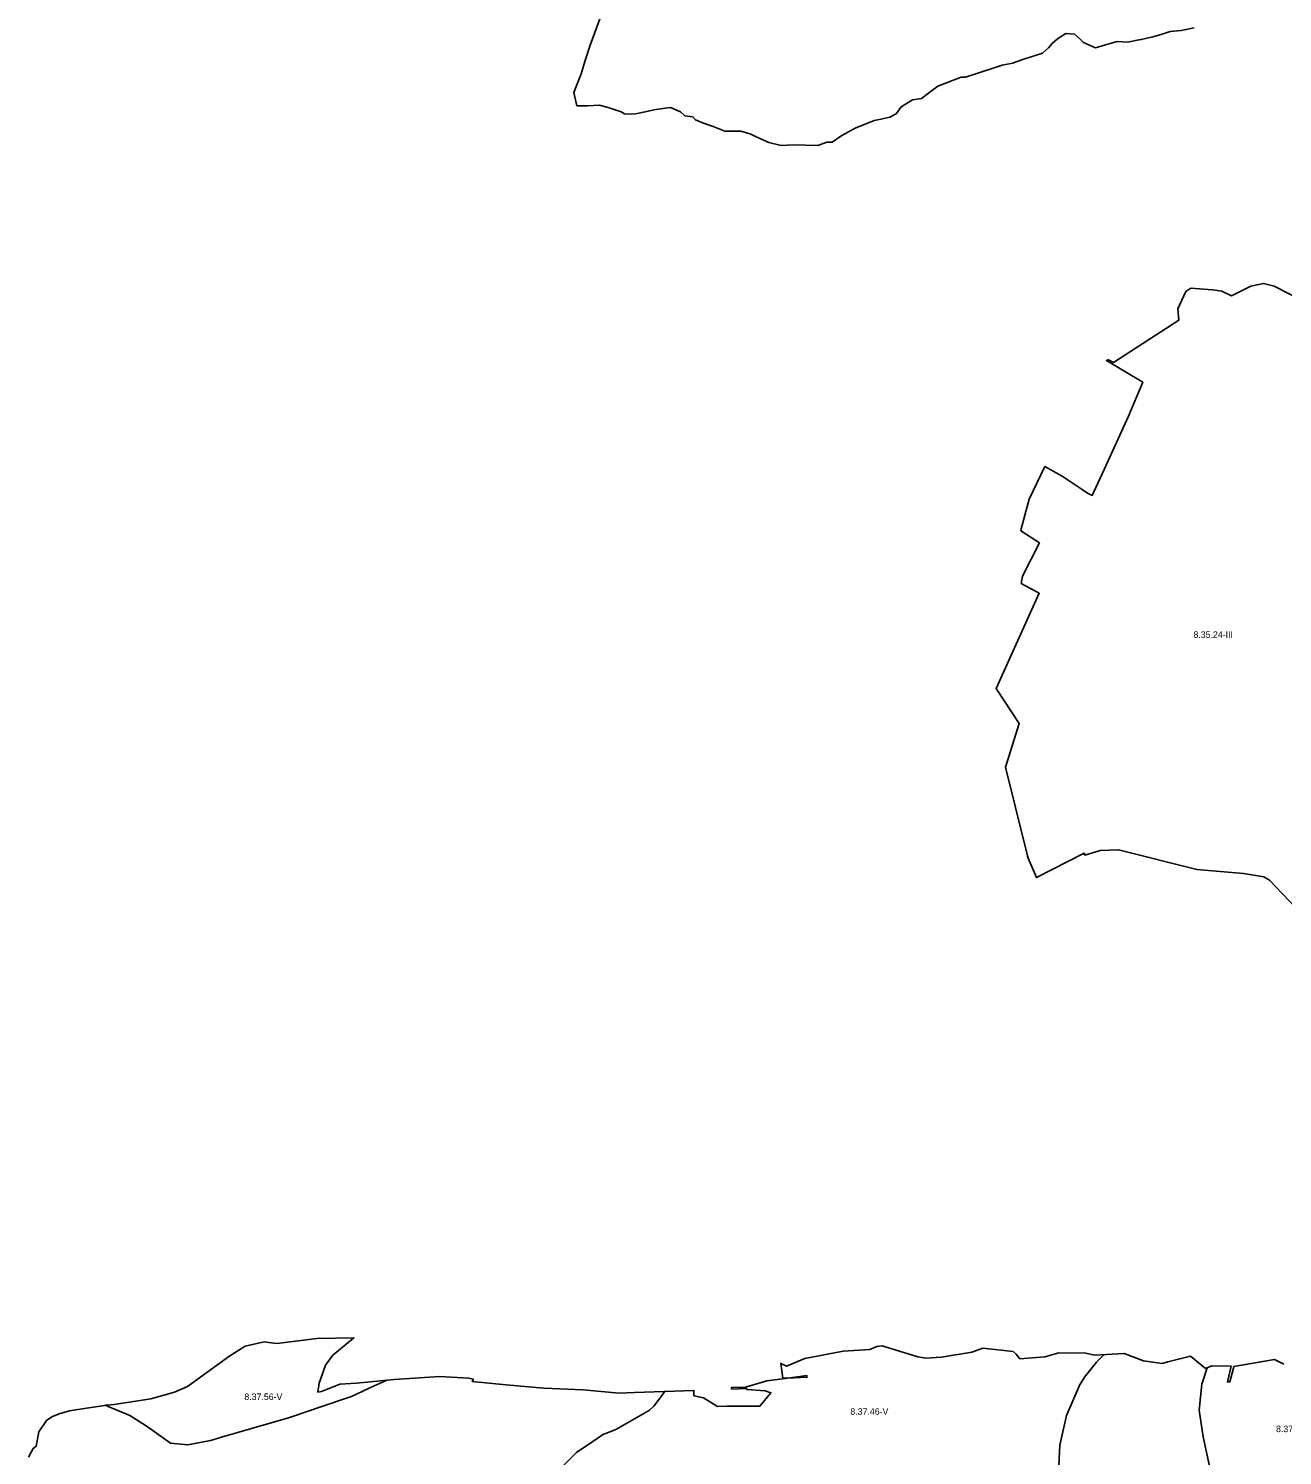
# Model space of a CAD drawing. Extents: x -547623 to -533936, y -1096714 to -1086523.
# Drawn here: x -544698 to -542784, y -1092367 to -1090189 of the extents above; entities that cross this region are included whole.
import ezdxf

# ---------------------------------------------------------------- set-up
doc = ezdxf.new("R2010")
doc.units = 0
doc.layers.add('Vrstva 27', color=7, linetype='Continuous')
doc.layers.add('Vrstva 28', color=7, linetype='Continuous')

msp = doc.modelspace()

# ---------------------------------------------------------------- linework, layer by layer
at = {"layer": 'Vrstva 28'}
for p, q in [((-543086, -1092247.5), (-543068, -1092224.5)), ((-543068, -1092224.5), (-543086, -1092247.5)), ((-543068, -1092224.5), (-543056.1, -1092213.1)), ((-543056.1, -1092213.1), (-543068, -1092224.5)), ((-542898.7, -1092233.1), (-542905.6, -1092253.4)), ((-542905.6, -1092253.4), (-542898.7, -1092233.1)), ((-544170.1, -1092260.9), (-544158.7, -1092255.7)), ((-544158.7, -1092255.7), (-544170.1, -1092260.9)), ((-544158.7, -1092255.7), (-544150.8, -1092252.1)), ((-544150.8, -1092252.1), (-544158.7, -1092255.7)), ((-543094.3, -1092260.6), (-543086, -1092247.5)), ((-543086, -1092247.5), (-543094.3, -1092260.6)), ((-542905.6, -1092253.4), (-542907, -1092257.5)), ((-542907, -1092257.5), (-542905.6, -1092253.4)), ((-544259.4, -1092295.4), (-544205, -1092277)), ((-544205, -1092277), (-544259.4, -1092295.4)), ((-544205, -1092277), (-544170.1, -1092260.9)), ((-544170.1, -1092260.9), (-544205, -1092277)), ((-543731.3, -1092275.6), (-543743, -1092291)), ((-543743, -1092291), (-543731.3, -1092275.6)), ((-543726.6, -1092269.4), (-543731.3, -1092275.6)), ((-543731.3, -1092275.6), (-543726.6, -1092269.4)), ((-543113.5, -1092306), (-543096, -1092264.6)), ((-543096, -1092264.6), (-543113.5, -1092306)), ((-543096, -1092264.6), (-543094.5, -1092261)), ((-543094.5, -1092261), (-543096, -1092264.6)), ((-543094.5, -1092261), (-543094.3, -1092260.6)), ((-543094.3, -1092260.6), (-543094.5, -1092261)), ((-542907, -1092258), (-542911, -1092298)), ((-542911, -1092298), (-542907, -1092258)), ((-542907, -1092257.5), (-542907, -1092258)), ((-542907, -1092258), (-542907, -1092257.5)), ((-544580.3, -1092290.3), (-544578.4, -1092290.1)), ((-544580.3, -1092290.3), (-544576, -1092292)), ((-544576, -1092292), (-544580.3, -1092290.3)), ((-544576, -1092292), (-544543, -1092306)), ((-544543, -1092306), (-544576, -1092292)), ((-544301, -1092309.5), (-544263.1, -1092296.7)), ((-544263.1, -1092296.7), (-544301, -1092309.5)), ((-544263.1, -1092296.7), (-544259.4, -1092295.4)), ((-544259.4, -1092295.4), (-544263.1, -1092296.7)), ((-543751.5, -1092299), (-543801.5, -1092327.5)), ((-543801.5, -1092327.5), (-543751.5, -1092299)), ((-543750, -1092297.6), (-543751.5, -1092299)), ((-543751.5, -1092299), (-543750, -1092297.6)), ((-543743, -1092291), (-543750, -1092297.6)), ((-543750, -1092297.6), (-543743, -1092291)), ((-542911, -1092298), (-542905, -1092338.5)), ((-542905, -1092338.5), (-542911, -1092298)), ((-544543, -1092306), (-544519.5, -1092320.5)), ((-544519.5, -1092320.5), (-544543, -1092306)), ((-544519.5, -1092320.5), (-544509.4, -1092327.7)), ((-544509.4, -1092327.7), (-544519.5, -1092320.5)), ((-544403.1, -1092339.1), (-544301, -1092309.5)), ((-544301, -1092309.5), (-544403.1, -1092339.1)), ((-543124, -1092351), (-543113.5, -1092306)), ((-543113.5, -1092306), (-543124, -1092351)), ((-544509.4, -1092327.7), (-544505.9, -1092330.2)), ((-544505.9, -1092330.2), (-544509.4, -1092327.7)), ((-544505.9, -1092330.2), (-544481, -1092348)), ((-544481, -1092348), (-544505.9, -1092330.2)), ((-544420, -1092344), (-544416.3, -1092342.9)), ((-544416.3, -1092342.9), (-544420, -1092344)), ((-544416.3, -1092342.9), (-544403.1, -1092339.1)), ((-544403.1, -1092339.1), (-544416.3, -1092342.9)), ((-543820, -1092334.5), (-543847.9, -1092353.3)), ((-543847.9, -1092353.3), (-543820, -1092334.5)), ((-543816.7, -1092333.3), (-543820, -1092334.5)), ((-543820, -1092334.5), (-543816.7, -1092333.3)), ((-543808.2, -1092330), (-543816.7, -1092333.3)), ((-543816.7, -1092333.3), (-543808.2, -1092330)), ((-543801.5, -1092327.5), (-543808.2, -1092330)), ((-543808.2, -1092330), (-543801.5, -1092327.5)), ((-542905, -1092338.5), (-542895.5, -1092383.5)), ((-542895.5, -1092383.5), (-542905, -1092338.5)), ((-544481, -1092348), (-544454.5, -1092350.5)), ((-544454.5, -1092350.5), (-544481, -1092348)), ((-544454.5, -1092350.5), (-544420, -1092344)), ((-544420, -1092344), (-544454.5, -1092350.5)), ((-543861.5, -1092362.5), (-543930, -1092430)), ((-543930, -1092430), (-543861.5, -1092362.5)), ((-543854.9, -1092358), (-543861.5, -1092362.5)), ((-543861.5, -1092362.5), (-543854.9, -1092358)), ((-543847.9, -1092353.3), (-543854.9, -1092358)), ((-543854.9, -1092358), (-543847.9, -1092353.3)), ((-543126, -1092393.1), (-543124, -1092351)), ((-543124, -1092351), (-543126, -1092393.1))]:
    msp.add_line(p, q, dxfattribs=at)
for points in [[(-542918.8, -1090188.4), (-542938.4, -1090192.3), (-542955.5, -1090194.2), (-542964.3, -1090197.2), (-542972.5, -1090199.7), (-542981.8, -1090202.3), (-542999.5, -1090206.3), (-543005.7, -1090207.4), (-543020.1, -1090210), (-543036.1, -1090209.4), (-543054, -1090214.5), (-543069.4, -1090218.8), (-543087.7, -1090210.8), (-543092.9, -1090205.8), (-543101.6, -1090198.2), (-543114.5, -1090196.9), (-543127.1, -1090205.1), (-543135.6, -1090212.4), (-543141.3, -1090219), (-543150.2, -1090227.2), (-543180, -1090236.7), (-543195.8, -1090242.2), (-543211.6, -1090245.3), (-543222.4, -1090248.7), (-543249, -1090257.4), (-543267.5, -1090263.5), (-543274.1, -1090263.7), (-543310, -1090277.2), (-543324.1, -1090288.3), (-543334.8, -1090296.2), (-543348.6, -1090298.5), (-543365.7, -1090308.8), (-543373.7, -1090319.5), (-543383.2, -1090324.7), (-543396.8, -1090327.6), (-543407.1, -1090329.8), (-543436.2, -1090341.3), (-543456.7, -1090352.7), (-543471.3, -1090363.1), (-543479.2, -1090362.6), (-543493.1, -1090368.1), (-543511.4, -1090367.5), (-543529.8, -1090366.7), (-543540, -1090367.3), (-543549.1, -1090367.7), (-543568, -1090363.5), (-543588.3, -1090354), (-543595.2, -1090350.8), (-543603.5, -1090348), (-543611, -1090345.9), (-543634.8, -1090346.1), (-543653, -1090338.7), (-543669, -1090333.4), (-543680, -1090328.6), (-543684, -1090324), (-543696.2, -1090322.6), (-543702.6, -1090316.4), (-543717.8, -1090309.8), (-543725.6, -1090310.8), (-543743.4, -1090313.7), (-543754.2, -1090316.2), (-543771.5, -1090319.6), (-543778.2, -1090320.3), (-543788, -1090319.4), (-543793, -1090316.5), (-543812.9, -1090310.2), (-543826.4, -1090306.3), (-543844.2, -1090307.4), (-543860.8, -1090307.4), (-543865.5, -1090287.1), (-543855.3, -1090261.1), (-543854, -1090257.1), (-543848.6, -1090239.8), (-543840.3, -1090214.6), (-543820.9, -1090161.1)], [(-542918.8, -1090188.4), (-542938.4, -1090192.3), (-542955.5, -1090194.2), (-542964.3, -1090197.2), (-542972.5, -1090199.7), (-542981.8, -1090202.3), (-542999.5, -1090206.3), (-543005.7, -1090207.4), (-543020.1, -1090210), (-543036.1, -1090209.4), (-543054, -1090214.5), (-543069.4, -1090218.8), (-543087.7, -1090210.8), (-543092.9, -1090205.8), (-543101.6, -1090198.2), (-543114.5, -1090196.9), (-543127.1, -1090205.1), (-543135.6, -1090212.4), (-543141.3, -1090219), (-543150.2, -1090227.2), (-543180, -1090236.7), (-543195.8, -1090242.2), (-543211.6, -1090245.3), (-543222.4, -1090248.7), (-543249, -1090257.4), (-543267.5, -1090263.5), (-543274.1, -1090263.7), (-543310, -1090277.2), (-543324.1, -1090288.3), (-543334.8, -1090296.2), (-543348.6, -1090298.5), (-543365.7, -1090308.8), (-543373.7, -1090319.5), (-543383.2, -1090324.7), (-543396.8, -1090327.6), (-543407.1, -1090329.8), (-543436.2, -1090341.3), (-543456.7, -1090352.7), (-543471.3, -1090363.1), (-543479.2, -1090362.6), (-543493.1, -1090368.1), (-543511.4, -1090367.5), (-543529.8, -1090366.7), (-543540, -1090367.3), (-543549.1, -1090367.7), (-543568, -1090363.5), (-543588.3, -1090354), (-543595.2, -1090350.8), (-543603.5, -1090348), (-543611, -1090345.9), (-543634.8, -1090346.1), (-543653, -1090338.7), (-543669, -1090333.4), (-543680, -1090328.6), (-543684, -1090324), (-543696.2, -1090322.6), (-543702.6, -1090316.4), (-543717.8, -1090309.8), (-543725.6, -1090310.8), (-543743.4, -1090313.7), (-543754.2, -1090316.2), (-543771.5, -1090319.6), (-543778.2, -1090320.3), (-543788, -1090319.4), (-543793, -1090316.5), (-543812.9, -1090310.2), (-543826.4, -1090306.3), (-543844.2, -1090307.4), (-543860.8, -1090307.4), (-543865.5, -1090287.1), (-543855.3, -1090261.1), (-543854, -1090257.1), (-543848.6, -1090239.8), (-543840.3, -1090214.6), (-543820.9, -1090161.1)], [(-542764.9, -1091529.8), (-542804, -1091488.8), (-542812.6, -1091483.8), (-542843.5, -1091479.1), (-542914.7, -1091472.6), (-543034.2, -1091442.6), (-543062, -1091443.7), (-543085.5, -1091450.7), (-543086.4, -1091447.9), (-543159.6, -1091485.1), (-543172.2, -1091455.6), (-543173.3, -1091452.1), (-543191.3, -1091378), (-543206.6, -1091316.7), (-543185.9, -1091250), (-543220.9, -1091196.4), (-543155.3, -1091051.1), (-543182.7, -1091036.3), (-543180.5, -1091024.9), (-543154.8, -1090974.3), (-543183.4, -1090955.8), (-543182.6, -1090952.7), (-543170.7, -1090907.4), (-543146.7, -1090857.8), (-543120.3, -1090872.7), (-543089.7, -1090892.7), (-543081.6, -1090898.6), (-543074.3, -1090901.8), (-543056.3, -1090862.5), (-543018.8, -1090780.9), (-542997.3, -1090729.3), (-543052.7, -1090696.2), (-543049.5, -1090694.9), (-543042, -1090699.3), (-542942.4, -1090634.5), (-542943.8, -1090617.1), (-542931.7, -1090590.7), (-542923.6, -1090585.5), (-542890.8, -1090588.1), (-542876.6, -1090590), (-542861.9, -1090597.3), (-542832.1, -1090582.7), (-542812.8, -1090578.3), (-542796.8, -1090582.4), (-542700.9, -1090631.2)], [(-544697.7, -1092369.8), (-544690.8, -1092356.1), (-544686.1, -1092352.9), (-544681.7, -1092330.7), (-544670.4, -1092313.6), (-544662, -1092308.1), (-544650.8, -1092303.4), (-544635.1, -1092299), (-544615.8, -1092295.6), (-544578.4, -1092290.1), (-544567, -1092289.4), (-544510.8, -1092280.6), (-544507.7, -1092279.7), (-544474.8, -1092270.4), (-544454.9, -1092261.6), (-544390.2, -1092215), (-544366.9, -1092200.3), (-544338.2, -1092193.8), (-544319.7, -1092195.9), (-544314.5, -1092195.4), (-544257.8, -1092188.4), (-544201, -1092187.6), (-544233.2, -1092214), (-544244.3, -1092229.1), (-544253.9, -1092256.8), (-544256, -1092270.2), (-544250.7, -1092269.2), (-544222.4, -1092258.2), (-544197, -1092256.8), (-544139.4, -1092250.9), (-544069.8, -1092246.3), (-544026.2, -1092248.8), (-544018.8, -1092250.7), (-544020.5, -1092254.2), (-543968.7, -1092259.2), (-543911.2, -1092264.3), (-543851.4, -1092266.8), (-543796.3, -1092271.7), (-543772.7, -1092270.9), (-543682.2, -1092268), (-543682.2, -1092275.9), (-543667.4, -1092279), (-543646.2, -1092292), (-543631.8, -1092291.9), (-543615.4, -1092291.8), (-543581.5, -1092291.6), (-543564.7, -1092271.2), (-543573.4, -1092268.5), (-543601.2, -1092266.3), (-543601.6, -1092264.8), (-543624.8, -1092265.6), (-543624.8, -1092263.5), (-543603.4, -1092262.9), (-543571, -1092253.1), (-543539.1, -1092249), (-543509.8, -1092247.5), (-543509.7, -1092245), (-543539.1, -1092248.9), (-543546.6, -1092249.2), (-543549.8, -1092226.6), (-543541, -1092230.8), (-543512.7, -1092218.9), (-543454.2, -1092207.6), (-543413.9, -1092205.3), (-543403.2, -1092200.5), (-543394.8, -1092199.6), (-543340.7, -1092216.7), (-543328.1, -1092218.7), (-543304.4, -1092217), (-543258.1, -1092209.4), (-543241.4, -1092203.1), (-543195.2, -1092208.5), (-543190.3, -1092212.4), (-543184.8, -1092219.5), (-543146.8, -1092216.4), (-543125.3, -1092210.4), (-543084.2, -1092210.7), (-543071.1, -1092213.9), (-543025.6, -1092211.2), (-542996.1, -1092222.6), (-542967.6, -1092226.4), (-542959.1, -1092224.3), (-542924.2, -1092215.4), (-542901.6, -1092234.3), (-542891.8, -1092230.4), (-542862.3, -1092230.5), (-542868.1, -1092254.6), (-542864.3, -1092254.4), (-542858.9, -1092233.8), (-542858.2, -1092231.1), (-542796.1, -1092220.6), (-542782, -1092227.4)]]:
    msp.add_lwpolyline(points, dxfattribs=at)

# ---------------------------------------------------------------- texts
at = {"layer": 'Vrstva 27'}
for s, p in [('8.35.24-III', (-542919.8, -1091119.4)), ('8.37.56-V', (-544368.3, -1092282.4)), ('8.37.46-V', (-543443.4, -1092304.9)), ('8.37.16-V', (-542793.8, -1092331.4))]:
    msp.add_text(s, height=10, dxfattribs=at).set_placement(p)

doc.saveas('drawing.dxf')
